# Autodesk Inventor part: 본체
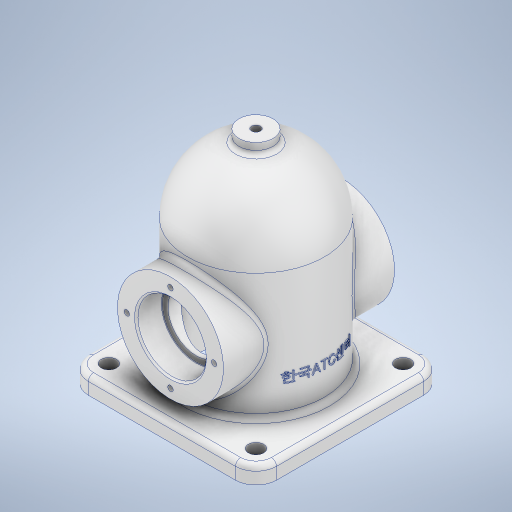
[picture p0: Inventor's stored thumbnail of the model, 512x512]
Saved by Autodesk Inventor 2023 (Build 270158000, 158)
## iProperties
Created: 2025-04
Part Number: 본체
Material: 알루미늄 6061
Document SubType Name: Modeling
Designer: ADMIN_PC
Density: 2.7 g/cm^3
Appearance: 알루미늄 - 평지
Mass: 865.91 g
Surface Area: 800.809 cm^2
Volume: 320.707 cm^3
Author: ADMIN_PC
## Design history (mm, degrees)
sketch "스케치1"
  geometry: L1 (-57.941, 0)-(9.657, 0) reference; L2 (0, -26.457)-(0, 158.741) reference; L3 (-40, 0)-(-40, 84); L4 (0, 84)-(0, 0); L5 (-40, 0)-(0, 0); L6 (0, 124)-(0, 84); A1 r 40 centre (0, 84) between (0, 124) and (-40, 84); 1 further point
  constraints: 8 end point, 3 collinear, 3 point on line, 2 point on circle, 1 centre point, 1 coincident, 1 vertical
  dimensions: "d0" = 40 radius of A1; "d1" = 84 distance of L3.start L3.end; "d2" = 40 distance of L3.start L4.end
revolve "회전1" sketch "스케치1" stored, may be unused: angle "d3" = 90 deg
sketch "스케치2"
  geometry: C1 r 10 at (0, 0); 1 further point
  constraints: 1 centre point, 1 coincident
  dimensions: "d4" = 20 diameter of C1
extrude "돌출1" join sketch "스케치2" distance "d5" = 129; taper "d6" = 0 deg
sketch "스케치5"
  geometry: L1 (70.565, 48)-(-94.644, 48); L2 (-40, 0)-(40, 0) reference; L3 (0, -16)-(0, 96) reference; C1 r 31 at (0, 48); 1 further point
  constraints: 2 end point, 2 point on line, 1 centre point, 1 horizontal
  dimensions: "d11" = 48 distance between parallel lines of L2 L1; "d12" = 62 diameter of C1
extrude "돌출2" join sketch "스케치5" stored distance "d13" = 100; taper "d14" = 0 deg
sketch "스케치8"
  geometry: L1 (-58.34, 0)-(75.198, 0); L2 (-40, -48)-(40, -48) reference; L3 (0, -73.8)-(0, 106.8) reference; C1 r 20 at (0, 0); 1 further point
  constraints: 2 end point, 2 point on line, 1 centre point, 1 horizontal
  dimensions: "d21" = 48 distance between parallel lines of L2 L1; "d22" = 40 diameter of C1
extrude "돌출4" cut sketch "스케치8" distance "d23" = 15; taper "d24" = 0 deg
sketch "스케치9"
  geometry: L1 (0, -73.8)-(0, 106.8) reference; L2 (-61.351, 0)-(68.471, 0); L3 (-40, -48)-(40, -48) reference; C1 r 16.5 at (0, 0); 1 further point
  constraints: 2 end point, 2 point on line, 1 centre point, 1 horizontal
  dimensions: "d25" = 33 diameter of C1; "d26" = 48 distance between parallel lines of L3 L2
extrude "돌출5" cut sketch "스케치9" extent not by distance; stored distance "d27" = 0; taper "d28" = 0 deg
sketch "스케치11"
  geometry: L1 (-56, 0)-(56, 0) reference; L2 (0, 56)-(0, -56) reference; 2 further points
  constraints: 1 coincident
hole "구멍1" sketch "스케치11" at (0, 0) diameter "d29" = 5.1881; stored, may be unused: countersink angle "d33" = 90 deg, drill point angle "d35" = 118 deg; dims "d30" = 20, "d31" = 4, "d32" = 2, "d34" = 16
sketch "스케치14"
  geometry: L1 (-61.351, 0)-(72.449, 0); L2 (-40, -48)-(40, -48) reference; L3 (0, -73.8)-(0, 106.8) reference; 2 further points
  constraints: 2 end point, 1 horizontal, 1 point on line
  dimensions: "d36" = 48 distance between parallel lines of L2 L1; "d37" = 51 diameter of point (0, 25.5) L1
hole "구멍2" sketch "스케치14" at (0, 25.5) diameter "d38" = 3.242; stored, may be unused: countersink angle "d42" = 90 deg, drill point angle "d44" = 118 deg; dims "d39" = 8, "d40" = 4, "d41" = 2, "d43" = 10
node "작업 평면1"
chamfer "모따기1" distance "d64" = 1; stored, may be unused: second distance "d65" = 2, angle "d66" = 45 deg
fillet "모깎기3" dims "d73" = 3
fillet "모깎기4" dims "d74" = 0.3
sketch "스케치23"
  geometry: L1 (55, 55)-(-55, 55); L2 (-55, 55)-(-55, -55); L3 (-55, -55)-(55, -55); L4 (55, -55)-(55, 55); L5 (55, 55)-(-55, -55); L6 (-55, 55)-(55, -55); C1 r 12.093 at (0, 0) reference; 1 further point
  constraints: 12 end point, 2 midpoint, 2 parallel, 1 horizontal, 1 perpendicular
  dimensions: "d75" = 110 distance of L3.end L2.end; "d76" = 110 distance of L2.end L1.end
extrude "돌출10" join sketch "스케치23" distance "d77" = 10; taper "d78" = 0 deg
sketch "스케치25"
  geometry: L1 (-24.8, 0)-(148.8, 0) reference; L2 (116, 0)-(0, 0); L3 (0, -2.594)-(0, 2.594) reference; L4 (0, 0)-(0, 32); L5 (0, 55)-(0, -55) reference; L6 (0, 32)-(84, 32); A1 r 40 centre (84, 0) between (84, -40) and (84, 40) reference; A2 r 32 centre (84, 0) between (116, 0) and (84, 32); 3 further points
  constraints: 6 end point, 3 point on circle, 2 midpoint, 2 point on line, 1 centre point, 1 perpendicular
  dimensions: "d80" = 84 distance of L4.end L6.end; "d82" = 32 distance of L2.end L4.end; "d84" = 116 distance of L2.start point (0, 0)
revolve "회전4" sketch "스케치25" stored, may be unused: angle "d85" = 90 deg
fillet "모깎기5" dims "d88" = 12
sketch "스케치28"
  geometry: C1 r 4.5 at (-43, -43); C2 r 4.5 at (-43, 43); C3 r 4.5 at (43, 43); C4 r 4.5 at (43, -43); A1 r 12 centre (-43, -43) between (-55, -43) and (-43, -55) reference; A2 r 12 centre (-43, 43) between (-43, 55) and (-55, 43) reference; A3 r 12 centre (43, 43) between (55, 43) and (43, 55) reference; A4 r 12 centre (43, -43) between (43, -55) and (55, -43) reference; 1 further point
  constraints: 4 centre point, 4 coincident
  dimensions: "d89" = 9 diameter of C1; "d90" = 9 diameter of C2; "d91" = 9 diameter of C3; "d92" = 9 diameter of C4
extrude "돌출11" cut sketch "스케치28" extent not by distance; stored distance "d93" = 119; taper "d94" = 0 deg
fillet "모깎기6" dims "d95" = 3
node "작업 평면3"
sketch "스케치30"
  geometry: L1 (0, -43)-(0, 43) reference; L2 (-25.8, 0)-(154.8, 0) reference; 2 further points
  constraints: 1 point on line, 1 other
  dimensions: "d97" = 30 distance from line of L1 point (30, 0)
feature "엠보싱2" sketch "스케치30" dims "d0" = 40, "d1" = 84, "d2" = 40, "d98" = 0.5, "d99" = 0
node "솔리드1"
mirror "미러1"
pattern_circular "원형 패턴1" dims angle "d46" = 360 deg
mirror "미러2"
feature "A9D066F2-1C7D-4E18-AEED-F7BC21143FA4" dims "d29" = 5.1881, "d30" = 20, "d31" = 4, "d32" = 2, "d33" = 90 deg, "d34" = 16, "d35" = 118 deg
